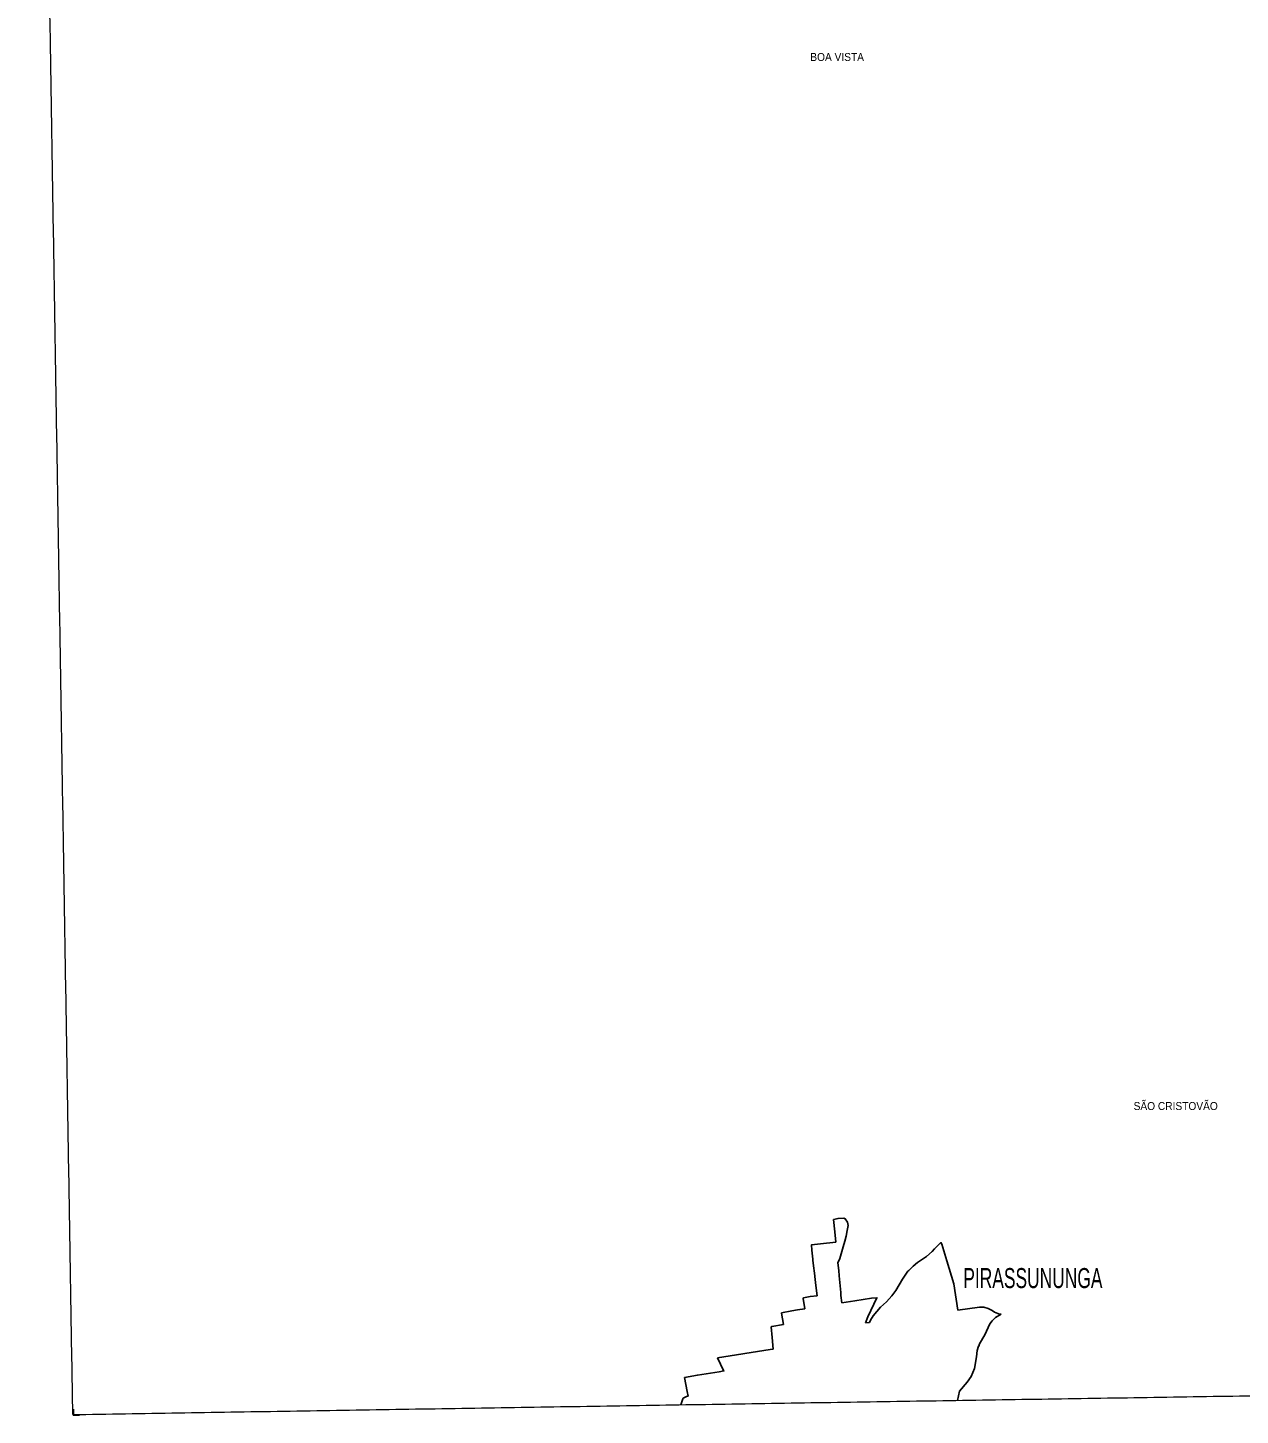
# Model space of a CAD drawing. Extents: x 241.4 to 267.7, y 7565 to 7593.1.
# Drawn here: x 241.43 to 253.55, y 7565.02 to 7578.89 of the extents above; entities that cross this region are included whole.
import ezdxf
from ezdxf.enums import TextEntityAlignment as Align

# ---------------------------------------------------------------- set-up
doc = ezdxf.new("R2010")
doc.units = 0
doc.header["$LTSCALE"] = 0.032
doc.layers.add('41', color=7, linetype='Continuous', lineweight=25)
doc.layers.add('63', color=7, linetype='Continuous', lineweight=13)
doc.layers.add('61', color=7, linetype='Continuous')

msp = doc.modelspace()

# ---------------------------------------------------------------- linework, layer by layer
at = {"layer": '41'}
for points in [[(249.6192, 7566.8698), (249.6253, 7566.9028), (249.6261, 7566.9222), (249.6204, 7566.9537), (249.5978, 7566.9885), (249.5857, 7566.9925), (249.5274, 7566.9917), (249.4813, 7566.9805), (249.4939, 7566.856), (249.504, 7566.7554), (249.3513, 7566.738), (249.2599, 7566.7275), (249.265, 7566.6745), (249.2737, 7566.5833)], [(249.5945, 7566.7657), (249.6089, 7566.8144), (249.6192, 7566.8698)], [(249.525, 7566.5476), (249.5428, 7566.5909), (249.5773, 7566.7074), (249.5945, 7566.7657)], [(250.4912, 7566.6865), (250.466, 7566.6616), (250.4102, 7566.6123), (250.3211, 7566.55), (250.2775, 7566.5152), (250.2338, 7566.4699), (250.2245, 7566.4658), (250.1897, 7566.414)], [(250.6135, 7566.5679), (250.5633, 7566.7345), (250.5548, 7566.7494), (250.4912, 7566.6865)], [(249.2737, 7566.5833), (249.2745, 7566.5749), (249.2812, 7566.5183), (249.2901, 7566.4428), (249.2972, 7566.3826), (249.3046, 7566.3201), (249.3165, 7566.2193)], [(249.5649, 7566.1463), (249.5559, 7566.2224), (249.5532, 7566.2526), (249.5441, 7566.3519), (249.5383, 7566.4161), (249.5327, 7566.4716), (249.525, 7566.5476)], [(250.7234, 7566.0753), (250.6828, 7566.338), (250.6135, 7566.5679)], [(250.1897, 7566.414), (250.1707, 7566.3857), (250.1043, 7566.2716), (250.0655, 7566.219), (250.0096, 7566.1584), (249.9514, 7566.105), (249.8776, 7566.0192), (249.8523, 7565.9755), (249.8394, 7565.9502), (249.7994, 7565.9467)], [(249.3165, 7566.2193), (249.2478, 7566.2111), (249.1808, 7566.1965), (249.1788, 7566.1907), (249.1934, 7566.088)], [(249.7994, 7565.9467), (249.8241, 7566.0072), (249.9156, 7566.1984), (249.8614, 7566.1929), (249.6948, 7566.1667), (249.5649, 7566.1463)], [(251.1574, 7566.0343), (251.1392, 7566.0354), (251.0898, 7566.0548), (251.068, 7566.0702), (251.0259, 7566.0912), (250.9838, 7566.1033), (250.9418, 7566.1058), (250.7234, 7566.0753)], [(249.1934, 7566.088), (249.1196, 7566.0764), (249.0635, 7566.0668), (248.9615, 7566.0493)], [(248.9615, 7566.0493), (248.9623, 7566.0442), (248.981, 7565.9311)], [(250.7203, 7565.1733), (250.7409, 7565.2651), (250.818, 7565.3543), (250.8557, 7565.4129), (250.8895, 7565.4916), (250.9111, 7565.6072), (250.9168, 7565.6731), (250.9288, 7565.7156), (250.932, 7565.7164), (250.9417, 7565.7389), (250.9947, 7565.8288), (251.0436, 7565.9381), (251.0661, 7565.9694), (251.0991, 7565.9999), (251.1574, 7566.0343)], [(248.981, 7565.9311), (248.8661, 7565.9125), (248.8573, 7565.9077), (248.8674, 7565.801), (248.8783, 7565.6847)], [(248.8783, 7565.6847), (248.8495, 7565.6812), (248.3201, 7565.5977)], [(248.3201, 7565.5977), (248.3825, 7565.4724), (248.3851, 7565.4671), (248.3382, 7565.4597)], [(248.3382, 7565.4597), (248.1212, 7565.4253), (247.9915, 7565.4023)], [(247.9915, 7565.4023), (248.0198, 7565.2612), (248.0268, 7565.2149)], [(247.9779, 7565.1939), (247.976, 7565.1888), (247.9683, 7565.1679), (247.9543, 7565.1294)], [(248.0268, 7565.2149), (248.0112, 7565.2114), (247.9779, 7565.1939)]]:
    msp.add_lwpolyline(points, dxfattribs=at)
at = {"layer": '63', "lineweight": 25}
msp.add_lwpolyline([(241.8838, 7565.0859), (241.8838, 7565.0243), (241.9445, 7565.0243)], dxfattribs=at)
at = {"layer": '63'}
for points in [[(241.8778, 7565.0311), (241.8686, 7565.5963), (241.8594, 7566.1614), (241.8501, 7566.7265), (241.8409, 7567.2916), (241.8317, 7567.8568), (241.8224, 7568.4219), (241.8132, 7568.987), (241.804, 7569.5521), (241.7947, 7570.1172), (241.7855, 7570.6824), (241.7763, 7571.2475), (241.7671, 7571.8126), (241.7579, 7572.3777), (241.7486, 7572.9428), (241.7394, 7573.508), (241.7302, 7574.0731), (241.721, 7574.6382), (241.7118, 7575.2033), (241.7026, 7575.7684), (241.6934, 7576.3336), (241.6842, 7576.8987), (241.675, 7577.4638), (241.6658, 7578.0289), (241.6566, 7578.594), (241.6474, 7579.1591), (241.6382, 7579.7243), (241.629, 7580.2894), (241.6198, 7580.8545), (241.6107, 7581.4196), (241.6015, 7581.9847), (241.5923, 7582.5498), (241.5831, 7583.115), (241.5739, 7583.6801), (241.5648, 7584.2452), (241.5556, 7584.8103), (241.5464, 7585.3754), (241.5373, 7585.9405), (241.5281, 7586.5056), (241.5189, 7587.0707), (241.5098, 7587.6359), (241.5006, 7588.201), (241.4914, 7588.7661), (241.4823, 7589.3312), (241.4731, 7589.8963), (241.464, 7590.4614), (241.4548, 7591.0265), (241.4457, 7591.5916), (241.4365, 7592.1567), (241.4274, 7592.7219)], [(241.8778, 7565.0311), (242.4049, 7565.0398), (242.9319, 7565.0484), (243.4589, 7565.0569), (243.9859, 7565.0655), (244.5129, 7565.074), (245.04, 7565.0826), (245.567, 7565.0911), (246.094, 7565.0995), (246.621, 7565.108), (247.148, 7565.1165), (247.675, 7565.1249), (248.202, 7565.1333), (248.729, 7565.1417), (249.256, 7565.1501), (249.783, 7565.1585), (250.31, 7565.1668), (250.837, 7565.1751), (251.364, 7565.1835), (251.891, 7565.1917), (252.418, 7565.2), (252.945, 7565.2083), (253.472, 7565.2165), (253.999, 7565.2247), (254.526, 7565.2329), (255.0529, 7565.2411), (255.5799, 7565.2493), (256.1069, 7565.2575), (256.6339, 7565.2656), (257.1609, 7565.2737), (257.6879, 7565.2818), (258.2148, 7565.2899), (258.7418, 7565.298), (259.2688, 7565.306), (259.7958, 7565.314), (260.3227, 7565.322), (260.8497, 7565.33), (261.3767, 7565.338), (261.9036, 7565.346), (262.4306, 7565.3539), (262.9576, 7565.3618), (263.4845, 7565.3697), (264.0115, 7565.3776), (264.5385, 7565.3855), (265.0654, 7565.3934), (265.5924, 7565.4012), (266.1193, 7565.409), (266.6463, 7565.4168), (267.1732, 7565.4246), (267.7002, 7565.4324)]]:
    msp.add_spline(points, degree=3, dxfattribs=at)

# ---------------------------------------------------------------- texts
at = {"layer": '61', "width": 0.95}
for s, p in [('BOA VISTA', (249.5173, 7578.5598)), ('SÃO CRISTOVÃO', (252.9013, 7568.075))]:
    msp.add_text(s, height=0.08, dxfattribs=at).set_placement(p, align=Align.CENTER)
at = {"layer": '61', "width": 0.65}
msp.add_text('PIRASSUNUNGA', height=0.2, dxfattribs=at).set_placement((250.7783, 7566.2953))

doc.saveas('drawing.dxf')
